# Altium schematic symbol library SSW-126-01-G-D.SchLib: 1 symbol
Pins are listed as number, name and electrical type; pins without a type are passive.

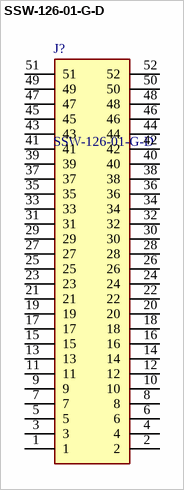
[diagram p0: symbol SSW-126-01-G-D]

## SSW-126-01-G-D
designator J?
52 Position, .100&quot; Tiger Buy&trade; Socket Strip; Manufacturer_Name: SAMTEC
footprint SSW-126-XX-YYY-D
pins: 1, 2, 3, 4, 5, 6, 7, 8, 9, 10, 11, 12, 13, 14, 15, 16, 17, 18, 19, 20, 21, 22, 23, 24, 25, 26, 27, 28, 29, 30, 31, 32, 33, 34, 35, 36, 37, 38, 39, 40, 41, 42, 43, 44, 45, 46, 47, 48, 49, 50, 51, 52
